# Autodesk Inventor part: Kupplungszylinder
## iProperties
Shininess: 20.0
Angle Display Precision: 2
Document Length Units: 11269
Document Angle Units: 11279
Document Time Units: 11290
Document Mass Units: 11283
Document Length Units Precision: 3
Document Angle Units Precision: 2
Created: 2003-02
Part Number: Kupplungszylinder
Material: S275JR
Document SubType Name: Modellieren
Designer: Administrator
Density: 0.0
Volumn: 0.0
Area: 0.0
PropertySet Name: Model Information
Control State: 0
Master: False
Checked Out: False
Author: Administrator
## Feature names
1. Grundkörper [Revolution]
2. Fase1 [Chamfer]
3. Rundung1 [Fillet]
4. Durchgangsbohrungen [Hole]
5. Passfedernut [Extrusion]
6. Gewindebohrung [Hole]
7. Rundung Innenkante [Fillet]
